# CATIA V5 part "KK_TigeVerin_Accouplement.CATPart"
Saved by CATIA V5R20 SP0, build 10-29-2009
Part number: Tige verin accouplement
Bounding box of the stored display mesh (mm): x -111.965 to 111.965, y 52.349 to 886.773, z -2710.767 to -1446.938
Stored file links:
  G:\Khaled_CFAO_2011\ST2M\ST2M_GR2\aboulegue\Khaled\CAD_thinkMOTION\KK_TigeVerin_Accouplement.CATPart
  G:\Khaled_CFAO_2011\ST2M\ST2M_GR2\aboulegue\Khaled\CAD_thinkMOTION\KK_Train_Atterrissage.CATProduct
  G:\Khaled_CFAO_2011\ST2M\ST2M_GR2\aboulegue\Khaled\CAD_thinkMOTION\KK_Squelette_TigeVerin.CATPart
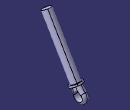
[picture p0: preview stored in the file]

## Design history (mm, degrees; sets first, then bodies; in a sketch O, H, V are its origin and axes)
External parameters (linked from other documents)
  `External.Longueur tige verin` = 1280 mm
Set1
  Plane1 "Plan reference": linked copy from another document
  Line1: linked copy from another document
  Point1 "Point.20": linked copy from another document
  Point2: linked copy from another document
Body1 (main body)
  Sketch1 on Plane1, origin (0, 0, 0), H (0, 1, 0), V (0, 0, 1)
    point P1 (121.3706, -1487.3415)
    line L1 (121.3706, -1487.3415) -> (687.1713, -2453.9177)
    line L2 (687.1713, -2453.9177) -> (783.8289, -2397.3376)
    line L3 (783.8289, -2397.3376) -> (767.6632, -2369.7212)
    line L4 (767.6632, -2369.7212) -> (740.0468, -2385.8869)
    line L5 (740.0468, -2385.8869) -> (190.4118, -1446.9271)
    line L6 (190.4118, -1446.9271) -> (121.3706, -1487.3415)
    reference projected line E1 (193.9888, -1611.3976) -> (840.6182, -2716.0561) from Line1
    reference projected point E2 (121.3706, -1487.3415) from Point1
    length L1 = 1120 {= `External.Longueur tige verin` -160mm}
    length L3 = 32
    length L6 = 80
    length L2 = 112
    perpendicularity: L2 L1
    parallelism: L3 L1, L4 L2, L5 L3, L6 L2
    coincidence: E1 L1, P1 E2
  Shaft1: profile Sketch1, axis Line1, angle 360
  Sketch2 on face of Shaft1 from Sketch1.L2, origin (0, 1232.0962, -2134.9373), H (-1, 0, 0), V (0, 0.863, 0.5052)
  Sketch3 on Plane1, origin (0, 0, 0), H (0, 1, 0), V (0, 0, 1)
    line L1 (770.0207, -2405.4205) -> (770.0207, -2405.4205)
    arc A1 centre (1161.364, -2176.3415) radius 453.4608 from (770.0207, -2405.4205) to (849.6732, -2505.6978) ccw
    arc A2 centre (768, -2592) radius 118.8216 from (849.6732, -2505.6978) to (828.0262, -2694.5448) cw
    point P5 (768, -2592)
    line L2 (828.0262, -2694.5448) -> (687.1713, -2453.9177)
    line L3 (687.1713, -2453.9177) -> (770.0207, -2405.4205)
    reference projected point E1 (768, -2592) from Point2
    reference projected line E2 (193.9888, -1611.3976) -> (840.6182, -2716.0561) from Line1
    reference projected line E3 (776.4246, -2401.6719) -> (583.1094, -2514.832) from edge [face of Shaft1 from Sketch1.L3 | face of Shaft1 from Sketch1.L2]
    length L3 = 96
    length L1 = 0
    radius A2 = 118.8216
    distance L3 E3 = 0
    tangency: A1 L1, A2 A1
    parallelism: L2 L1
    perpendicularity: L3 L1
    coincidence: P5 L2, P5 E1, E2 L2
  Pad1: profile Sketch3, direction (1, 0, 0), length 56, mirrored extent
  Mirror1: of Pad1, about face of Pad1 from Sketch3.L2
  Fillet1: radius 56, on edge [face of Mirror1 | face of Mirror1]
  Fillet2: radius 56, on edge [face of Mirror1 | face of Mirror1]
  Sketch4 on face of Mirror1, origin (-56, 0, 0), H (0, -1, 0), V (0, 0, 1)
  Sketch5 on face of Mirror1, origin (56, 0, 0), H (0, 1, 0), V (0, 0, 1)
  Sketch6 on face of Mirror1, origin (56, 0, 0), H (0, 1, 0), V (0, 0, 1)
    circle A1 centre (768, -2592) radius 80
    point P1 (768, -2592)
    reference projected point E1 (768, -2592) from Point2
    radius A1 = 80
    coincidence: E1 P1
  Pocket1: profile Sketch6, direction (-1, 0, 0), through (limit type 3)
